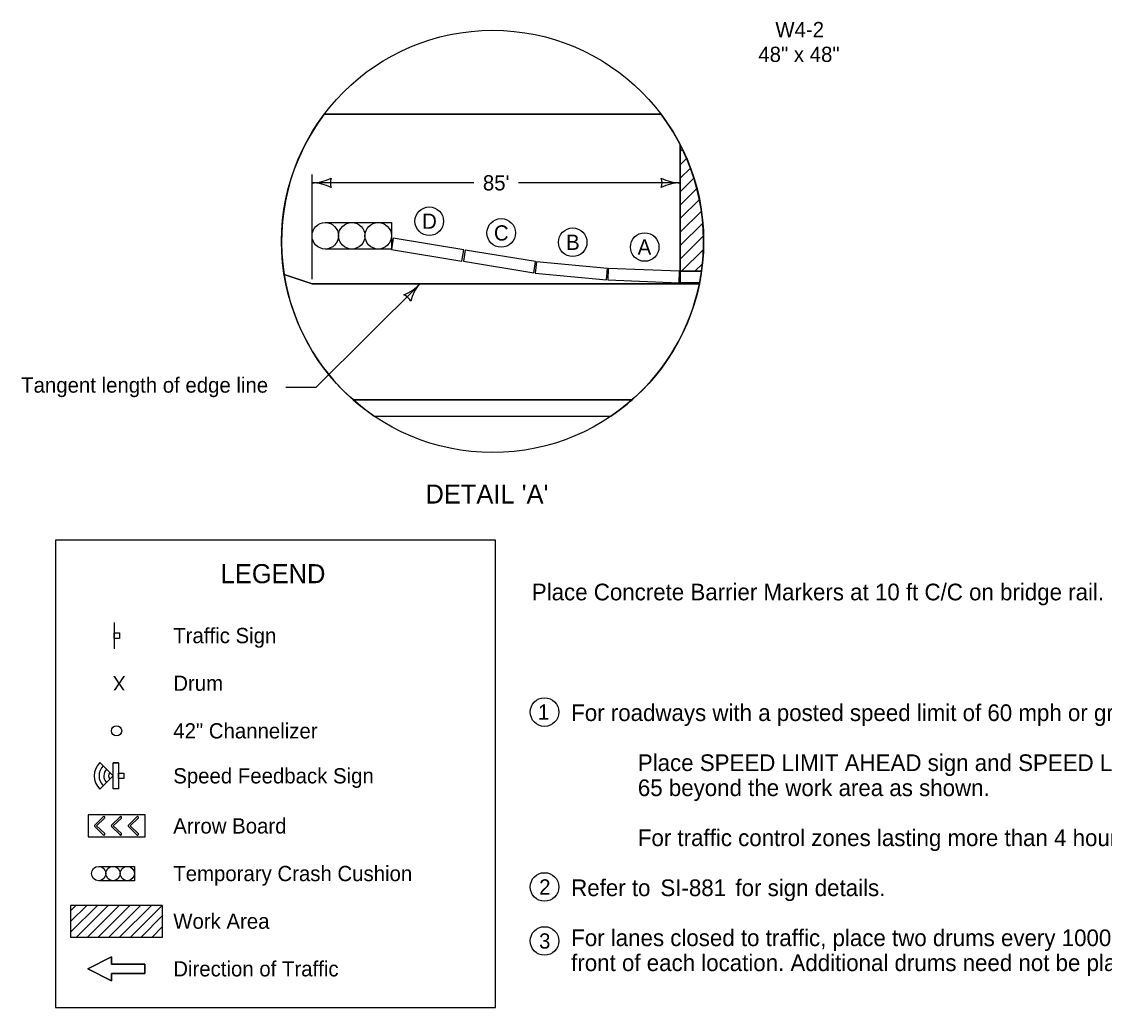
# Model space of a CAD drawing. Extents: x 10134 to 13311, y 7934 to 9733.
# Drawn here: x 10172 to 11309, y 7969 to 9003 of the extents above; entities that cross this region are included whole.
import ezdxf

# ---------------------------------------------------------------- set-up
doc = ezdxf.new("R2010")
doc.units = 0
for name, color, linetype in [('dsnCellElements', 7, 'Continuous'), ('dsnNonPlotable', 7, 'Continuous'), ('dsnStdDimension', 7, 'Continuous'), ('dsnstdModifiedBlock', 7, 'Continuous'), ('dsnStdNote', 7, 'Continuous'), ('dsnStdShading', 7, 'Continuous'), ('SheetText', 7, 'Continuous')]:
    doc.layers.add(name, color=color, linetype=linetype)

msp = doc.modelspace()

# ---------------------------------------------------------------- linework, layer by layer
at = {"layer": 'dsnCellElements'}
for p, q in [((10268.9, 8372.5), (10268.9, 8345)), ((10273.7, 8225.4), (10273.7, 8197.9)), ((10248.8, 8159.8), (10257.6, 8168.6)), ((10266.4, 8159.8), (10275.2, 8168.6)), ((10284, 8159.8), (10292.8, 8168.6)), ((10252.8, 8116.6), (10290.3, 8116.6)), ((10290.3, 8116.6), (10290.3, 8101.6)), ((10290.3, 8101.6), (10252.8, 8101.6)), ((10223.3, 8070.1), (10228.9, 8075.7)), ((10223.3, 8058.8), (10240.2, 8075.7)), ((10223.3, 8047.5), (10251.5, 8075.7)), ((10229.6, 8042.4), (10262.9, 8075.7)), ((10240.9, 8042.4), (10274.2, 8075.7)), ((10252.2, 8042.4), (10285.5, 8075.7)), ((10263.5, 8042.4), (10296.8, 8075.7)), ((10274.8, 8042.4), (10308.1, 8075.7)), ((10286.1, 8042.4), (10319.4, 8075.7)), ((10297.5, 8042.4), (10319.9, 8064.9)), ((10308.8, 8042.4), (10319.9, 8053.6))]:
    msp.add_line(p, q, dxfattribs=at)
for points in [[(10269, 8356), (10269, 8361.7), (10274.7, 8361.7), (10274.7, 8356)], [(10268, 8197.9), (10268, 8225.4), (10273.7, 8225.4), (10273.7, 8197.9)], [(10273.7, 8209), (10273.7, 8214.6), (10279.3, 8214.6), (10279.3, 8209)], [(10301.6, 8170.6), (10241.6, 8170.6), (10241.6, 8147.6), (10301.6, 8147.6)], [(10223.3, 8075.7), (10223.3, 8042.4), (10319.9, 8042.4), (10319.9, 8075.7)], [(10301.3, 8014.1), (10301.3, 8004.1), (10266.3, 8004.1), (10266.3, 7996.6), (10241.3, 8009.1), (10266.3, 8021.6), (10266.3, 8014.1)]]:
    msp.add_lwpolyline(points, close=True, dxfattribs=at)
for points in [[(10259.1, 8167.2), (10259, 8167.1), (10250.6, 8159.1), (10259.1, 8151)], [(10276.6, 8167.2), (10276.6, 8167.1), (10268.1, 8159.1), (10276.6, 8151)], [(10294.3, 8167.2), (10294.2, 8167.1), (10285.7, 8159.1), (10294.2, 8151)], [(10257.6, 8149.5), (10257.6, 8149.6), (10248.8, 8158.4), (10248.8, 8158.4)], [(10275.2, 8149.5), (10275.2, 8149.6), (10266.4, 8158.4), (10266.3, 8158.4)], [(10292.8, 8149.5), (10292.8, 8149.6), (10284, 8158.4), (10284, 8158.4)], [(10266.3, 8014.1), (10266.3, 8021.6), (10241.3, 8009.1), (10266.3, 7996.6), (10266.3, 8004.1), (10301.3, 8004.1), (10301.3, 8014.1), (10266.3, 8014.1)]]:
    msp.add_lwpolyline(points, dxfattribs=at)
for centre, radius in [((10490.7, 8778.6), 13.9), ((10518.5, 8778.6), 13.9), ((10546.3, 8778.6), 13.9), ((10271.6, 8258.9), 5.37), ((10271.6, 8258.9), 5.37), ((10252.8, 8109.1), 7.5), ((10252.8, 8109.1), 7.5), ((10267.8, 8109.1), 7.5), ((10267.8, 8109.1), 7.5), ((10282.8, 8109.1), 7.5), ((10282.8, 8109.1), 7.5)]:
    msp.add_circle(centre, radius, dxfattribs=at)
for centre, start, end in [((10258.4, 8167.9), 315.0975, 135.281), ((10275.9, 8167.9), 315.0975, 135.281), ((10293.5, 8167.9), 315.0975, 135.281), ((10249.5, 8159.1), 134.1616, 224.6098), ((10258.4, 8150.3), 226.201, 47.3602), ((10267.1, 8159.1), 134.1616, 224.6098), ((10275.9, 8150.3), 226.201, 47.3602), ((10284.7, 8159.1), 134.1616, 224.6098), ((10293.5, 8150.3), 226.201, 47.3602)]:
    msp.add_arc(centre, 1.03, start, end, dxfattribs=at)
at = {"layer": 'dsnNonPlotable'}
for p, q in [((10490.7, 8792.5), (10560.2, 8792.5)), ((10560.2, 8792.5), (10560.2, 8764.7)), ((10560.2, 8764.7), (10490.7, 8764.7)), ((10559.6, 8763.5), (10559.6, 8763.5)), ((10253.9, 8225.8), (10268, 8211.7)), ((10273.7, 8225.4), (10268, 8225.4)), ((10268, 8211.7), (10253.9, 8197.5)), ((10273.7, 8197.9), (10268, 8197.9))]:
    msp.add_line(p, q, dxfattribs=at)
for centre in [(10490.7, 8778.6), (10490.7, 8778.6), (10518.5, 8778.6), (10518.5, 8778.6), (10546.3, 8778.6), (10546.3, 8778.6)]:
    msp.add_circle(centre, 13.9, dxfattribs=at)
for radius, start, end in [(20.3, 135.88, 224.0313), (15.3, 136.1665, 223.7159), (10.3, 136.7294, 223.0963), (5.32, 138.7005, 221.2995)]:
    msp.add_arc((10268.5, 8211.7), radius, start, end, dxfattribs=at)
at = {"layer": 'dsnStdDimension'}
msp.add_line((10863.5, 8745.9), (10863.5, 8842.9), dxfattribs=at)
at = {"layer": 'dsnstdModifiedBlock'}
for p, q in [((10489.5, 8906.1), (10843.3, 8906.1)), ((10863.5, 8741.3), (10863.5, 8873.8)), ((10863.5, 8867.3), (10865.7, 8869.5)), ((10863.5, 8853.2), (10870.1, 8859.8)), ((10863.5, 8839.1), (10874.2, 8849.7)), ((10863.5, 8824.9), (10877.8, 8839.1)), ((10863.5, 8810.8), (10880.9, 8828.1)), ((10863.5, 8796.6), (10883.6, 8816.6)), ((10863.5, 8782.5), (10885.6, 8804.6)), ((10863.5, 8768.3), (10887.1, 8791.9)), ((10863.5, 8754.2), (10887.9, 8778.5)), ((10864.8, 8741.3), (10887.8, 8764.3)), ((10878.9, 8741.3), (10886.7, 8749.1)), ((10447.5, 8737.8), (10476.8, 8728.3)), ((10476.8, 8728.3), (10883.5, 8728.3)), ((10519.8, 8606.5), (10812.9, 8606.5))]:
    msp.add_line(p, q, dxfattribs=at)
for points in [[(10636.1, 8763.9), (10562.1, 8776), (10560.2, 8764.1), (10634.2, 8752)], [(10711.6, 8751.5), (10637.6, 8763.6), (10635.7, 8751.8), (10709.7, 8739.6)], [(10787, 8744.3), (10712.4, 8751.4), (10711.2, 8739.4), (10785.9, 8732.3)], [(10862.8, 8741.3), (10787.9, 8744.3), (10787.4, 8732.3), (10862.3, 8729.3)]]:
    msp.add_lwpolyline(points, close=True, dxfattribs=at)
for points in [[(10883.7, 8729.3), (10863.5, 8729.3), (10863.5, 8741.3), (10885.7, 8741.3)], [(10207.5, 8458.9), (10207.5, 7968.6), (10669.4, 7968.6), (10669.4, 8458.9), (10207.5, 8458.9)]]:
    msp.add_lwpolyline(points, dxfattribs=at)
at = {"layer": 'dsnStdNote'}
for centre in [(10599.9, 8793.9), (10675.4, 8781.6), (10750.5, 8771.8), (10826.1, 8766.8), (10720.9, 8278.6), (10720.9, 8095), (10720.9, 8038.3)]:
    msp.add_circle(centre, 15, dxfattribs=at)
at = {"layer": 'dsnStdShading'}
for p, q in [((10843.3, 8906.1), (10489.5, 8906.1)), ((10447.5, 8737.8), (10476.8, 8728.3)), ((10476.8, 8728.3), (10447.5, 8737.8)), ((10863.5, 8741.3), (10885.7, 8741.3)), ((10476.8, 8728.3), (10883.5, 8728.3)), ((10883.5, 8728.3), (10476.8, 8728.3)), ((10519.8, 8606.5), (10812.9, 8606.5)), ((10812.9, 8606.5), (10519.8, 8606.5)), ((10542.1, 8589.2), (10790.6, 8589.2))]:
    msp.add_line(p, q, dxfattribs=at)
for points in [[(10863.5, 8873.8), (10863.5, 8834.2), (10863.5, 8741.3)], [(10636.1, 8763.9), (10562.1, 8776), (10560.2, 8764.1), (10634.2, 8752), (10636.1, 8763.9)], [(10711.6, 8751.5), (10637.6, 8763.6), (10635.7, 8751.8), (10709.7, 8739.6), (10711.6, 8751.5)], [(10787, 8744.3), (10712.4, 8751.4), (10711.2, 8739.4), (10785.9, 8732.3), (10787, 8744.3)], [(10862.8, 8741.3), (10787.9, 8744.3), (10787.4, 8732.3), (10862.3, 8729.3), (10862.8, 8741.3)], [(10885.7, 8741.3), (10863.5, 8741.3), (10863.5, 8729.3), (10883.7, 8729.3)], [(10883.7, 8729.3), (10863.5, 8729.3), (10863.5, 8741.3), (10885.7, 8741.3)]]:
    msp.add_lwpolyline(points, dxfattribs=at)
for start, end in [(142.9773, 189.0659), (351.8621, 37.0227), (351.8621, 27.1505), (189.0659, 228.5906), (348.7138, 351.8621), (311.4094, 348.45), (348.45, 348.7138), (228.5906, 235.889), (304.111, 311.4094)]:
    msp.add_arc((10666.4, 8772.7), 221.6, start, end, dxfattribs=at)
at = {"layer": 'SheetText'}
for p, q in [((10476.8, 8732.9), (10476.8, 8842.9)), ((10646.8, 8834.2), (10476.8, 8834.2)), ((10863.5, 8834.2), (10693.5, 8834.2)), ((10863.5, 8745.9), (10863.5, 8842.9)), ((10590.2, 8728.3), (10481.3, 8619.7)), ((10449.3, 8619.7), (10481.3, 8619.7))]:
    msp.add_line(p, q, dxfattribs=at)
msp.add_circle((10666.4, 8772.7), 221.6, dxfattribs=at)
for centre, radius, start, end in [((10476.8, 8876.7), 42.5, 270, 298.0725), ((10476.8, 8791.7), 42.5, 61.9275, 90), ((10512.5, 8834.2), 16.4, 162.2666, 197.7334), ((10827.9, 8834.2), 16.4, 342.2666, 17.7334), ((10863.5, 8876.7), 42.5, 241.9275, 270), ((10863.5, 8791.7), 42.5, 90, 118.0725), ((10558.2, 8756.5), 42.5, 290.4723, 318.5448), ((10621.9, 8700.2), 42.5, 138.5448, 166.6173), ((10566.5, 8701.6), 16.4, 30.8115, 66.2782)]:
    msp.add_arc(centre, radius, start, end, dxfattribs=at)

# ---------------------------------------------------------------- texts
at = {"layer": 'dsnCellElements'}
for s, height, p in [("DETAIL 'A'", 20, (10595.9, 8497.5)), ('LEGEND', 20, (10380.9, 8413.9)), ('Traffic Sign', 16, (10331.1, 8350.9)), ('Drum', 16, (10331.1, 8300.9)), ('42" Channelizer ', 16, (10331.1, 8250.9)), ('Speed Feedback Sign', 16, (10331.1, 8203.7)), ('Arrow Board', 16, (10331.1, 8151.1)), ('Temporary Crash Cushion', 16, (10331.1, 8101.1)), ('Work Area', 16, (10331.1, 8051.1)), ('Direction of Traffic', 16, (10331.1, 8001.1))]:
    msp.add_text(s, height=height, dxfattribs=at).set_placement(p)
msp.add_text('X', height=15, rotation=180, dxfattribs=at).set_placement((10281, 8316.4))
at = {"layer": 'dsnStdNote'}
for s, height, p in [('D', 16, (10592.4, 8785.9)), ('C', 16, (10667.8, 8773.6)), ('B', 16, (10743.6, 8763.8)), ('A', 16, (10818.7, 8758.8)), ('Place Concrete Barrier Markers at 10 ft C/C on bridge rail.', 17.5, (10707.6, 8395.9)), ('1', 16, (10714, 8270.6)), ('2', 16, (10715.3, 8087)), ('3', 16, (10715.2, 8030.3))]:
    msp.add_text(s, height=height, dxfattribs=at).set_placement(p)
at = {"layer": 'SheetText'}
for s, height, p in [('W4-2', 16, (10963.3, 8987.1)), ('48" x 48"', 16, (10945.4, 8961.1)), ("85'", 16, (10656.2, 8826.2)), ('Tangent length of edge line', 16, (10171.4, 8613.9)), ('For roadways with a posted speed limit of 60 mph or greater before road work:', 17.5, (10748.9, 8269.2)), ('Place SPEED LIMIT AHEAD sign and SPEED LIMIT 55 sign prior to the lane closure as shown. Place SPEED LIMIT', 17.5, (10818.9, 8216.7)), ('65 beyond the work area as shown.', 17.5, (10818.9, 8190.4)), ('For traffic control zones lasting more than 4 hours, place a Speed Feedback Sign at the end of the merge taper.', 17.5, (10818.9, 8137.9)), ('Refer to ', 17.5, (10748.9, 8085.4)), ('SI-881 ', 17.5, (10842.6, 8085.4)), ('for sign details.', 17.5, (10921.4, 8085.4)), ('For lanes closed to traffic, place two drums every 1000 feet. For full depth excavations in a closed lane, place two drums in ', 17.5, (10748.9, 8032.9)), ('front of each location. Additional drums need not be placed for full depth excavations spaced closer than 150 feet.', 17.5, (10748.9, 8006.7))]:
    msp.add_text(s, height=height, dxfattribs=at).set_placement(p)

doc.saveas('drawing.dxf')
